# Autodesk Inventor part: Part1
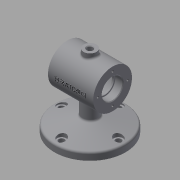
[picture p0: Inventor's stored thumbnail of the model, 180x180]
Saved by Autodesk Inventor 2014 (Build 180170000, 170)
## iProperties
Created: 2018-12
Part Number: Part1
Material: Generic
Document SubType Name: Modeling
Designer: kh
Density: 1 g/cm^3
Appearance: Default
Author: kh
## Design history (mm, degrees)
sketch "Sketch1"
  geometry: C1 r 55 at (0, 0); 1 further point
  constraints: 1 centre point, 1 coincident
  dimensions: "d0" = 110 diameter of C1
extrude "Extrusion1" new body sketch "Sketch1" distance "d1" = 11; taper "d2" = 0 deg
sketch "Sketch2"
  geometry: L1 (-59.309, 75)-(74.881, 75); L2 (-55, 0)-(55, 0) reference; L3 (-35, 75)-(35, 75); L4 (35, 75)-(35, 105); L5 (35, 105)-(-35, 105); L6 (-35, 105)-(-35, 75); L7 (0, 0)-(0, 105)
  constraints: 12 end point, 2 horizontal, 2 parallel, 2 perpendicular, 1 midpoint, 1 point on line, 1 other
  dimensions: "d4" = 75 distance between parallel lines of L2 L1; "d5" = 60 diameter of L5 L1; "d6" = 70 distance between parallel lines of L4 L6
revolve "Revolution1" sketch "Sketch2" stored, may be unused: angle "d7" = 90 deg
sketch "Sketch3"
  geometry: C1 r 12 at (0, 0); 1 further point
  constraints: 1 centre point, 1 coincident
  dimensions: "d8" = 24 diameter of C1
extrude "Extrusion2" join sketch "Sketch3" stored distance "d9" = 10; taper "d10" = 0 deg
sketch "Sketch4"
  geometry: L1 (12, 11)-(12, 45) reference; L2 (55, 11)-(-55, 11) reference; L3 (-12, 11)-(-12, 45) reference; L4 (0, 25.737)-(55, 11); L5 (-35, 105)-(35, 105) reference; L6 (0, 0)-(0, 105); L7 (0, 11)-(55, 11); L8 (0, 25.737)-(0, 11)
  constraints: 8 end point, 2 collinear, 2 midpoint, 2 point on line
  dimensions: "d11" = 165 deg angle of L2 L4
revolve "Revolution2" sketch "Sketch4" stored, may be unused: angle "d12" = 90 deg
sketch "Sketch6"
  geometry: L1 (-63.947, 75)-(66.267, 75); L2 (-35, 105)-(35, 105) reference; L3 (-35, 45)-(35, 45) reference; L4 (-55, 0)-(55, 0) reference; L5 (-35, 45)-(-35, 105) reference; L6 (35, 45)-(35, 105) reference; L7 (-35, 75)-(-23, 75); L8 (-23, 75)-(-23, 90.7); L9 (-23.3, 91)-(-35, 91); L10 (-35, 91)-(-35, 75); L11 (-23, 75)-(-20, 75); L12 (-20, 75)-(-20, 89); L13 (-20, 89)-(-23, 89); L14 (-23, 89)-(-23, 75); L15 (-20, 75)-(20, 75); L16 (20, 75)-(20, 97); L17 (17, 100)-(-17, 100); L18 (-20, 97)-(-20, 75); L19 (20, 75)-(23, 75); L20 (23, 75)-(23, 90.7); L21 (23, 89)-(20, 89); L22 (20, 89)-(20, 75); L23 (23, 75)-(35, 75); L24 (35, 75)-(35, 91); L25 (35, 91)-(23.3, 91); L26 (23, 91)-(23, 75); A1 r 0.3 centre (-23.3, 90.7) between (-23, 90.7) and (-23.3, 91); A2 r 0.3 centre (23.3, 90.7) between (23.3, 91) and (23, 90.7); A3 r 3 centre (-17, 97) between (-17, 100) and (-20, 97); A4 r 3 centre (17, 97) between (20, 97) and (17, 100); 4 further points
  constraints: 42 end point, 10 parallel, 9 point on line, 8 point on circle, 8 tangent, 6 horizontal, 5 perpendicular, 4 centre point, 2 equal radius, 1 midpoint
  dimensions: "d13" = 150 diameter of L4 L1; "d14" = 32 diameter of L9 L1; "d15" = 28 diameter of L13 L1; "d16" = 50 diameter of L17 L1; "d17" = 32 diameter of L25 L1; "d18" = 28 diameter of L21 L1; "d19" = 40 distance of point (20, 100) point (-20, 100); "d20" = 12 distance of point (-23, 91) L9.end; "d21" = 3 distance of L12.end L13.end; "d22" = 3 distance of L21.start L21.end; "d23" = 0.3 radius of A1; "d24" = 3 radius of A3
revolve "Revolution3" sketch "Sketch6" stored, may be unused: angle "d25" = 90 deg
sketch "Sketch8" dims "d27" = 88
  geometry: L1 (0, 0)-(0, 44); C1 r 4.5 at (0, 44); 2 further points
  constraints: 3 coincident, 2 end point, 1 centre point, 1 vertical, 1 vertical alignment, 2 other
  dimensions: "d28" = 9 diameter of C1
extrude "Extrusion3" cut sketch "Sketch8" distance "d29" = 16; taper "d30" = 0 deg
workplane "Work Plane3"
sketch "Sketch11"
  geometry: C1 r 4.5 at (0, 44) reference; C2 r 7 at (0, 44); 1 further point
  constraints: 1 centre point, 1 coincident
  dimensions: "d35" = 14 diameter of C2
extrude "Extrusion4" cut sketch "Sketch11" distance "d36" = 6; taper "d37" = 0 deg
pattern_circular "Circular Pattern1" dims angle "d39" = 360 deg
sketch "Sketch12" dims "d41" = 46
  geometry: L1 (0, 0)-(23, 0); C1 r 16 at (0, 0) reference; C2 r 30 at (0, 0) reference; 2 further points
  constraints: 2 coincident, 2 end point, 1 horizontal, 1 horizontal alignment, 2 other
hole "Hole1" sketch "Sketch12" at (23, 0) diameter "d42" = 3.242; stored, may be unused: countersink angle "d46" = 90 deg, drill point angle "d48" = 118 deg; dims "d43" = 8, "d44" = 4, "d45" = 2, "d47" = 10
pattern_circular "Circular Pattern2" dims angle "d50" = 360 deg
mirror "Mirror1"
workplane "Work Plane4"
sketch "Sketch13"
  geometry: L1 (0, 0)-(0, 55); C1 r 10 at (0, 0); C2 r 5 at (0, 0); 1 further point
  constraints: 2 centre point, 2 coincident, 2 end point, 1 vertical, 1 vertical alignment, 1 other
  dimensions: "d53" = 20 diameter of C1; "d54" = 10 diameter of C2
extrude "Extrusion5" join sketch "Sketch13" stored distance "d55" = 6; taper "d56" = 0 deg
sketch "Sketch14"
  geometry: C1 r 4.5 at (0, 0); 1 further point
  constraints: 1 centre point, 1 coincident
  dimensions: "d57" = 9 diameter of C1
extrude "Extrusion6" cut sketch "Sketch14" stored distance "d58" = 6; taper "d59" = 0 deg
chamfer "Chamfer1" distance "d60" = 1; stored, may be unused: second distance "d61" = 2, angle "d62" = 45 deg
workplane "Work Plane5"
sketch "Sketch15"
  geometry: L1 (-24.887, 3.602)-(24.887, 3.602); L2 (24.887, 3.602)-(24.887, -3.602); L3 (24.887, -3.602)-(-24.887, -3.602); L4 (-24.887, -3.602)-(-24.887, 3.602); L5 (-24.887, 3.602)-(24.887, -3.602); L6 (-35, 30)-(-35, -30) reference; L7 (35, 30)-(-35, 30) reference; 2 further points
  constraints: 2 end point, 1 midpoint, 2 other
  dimensions: "d63" = 35 distance from line of point (0, 0) L6; "d64" = 30 distance from line of point (0, 0) L7
emboss "Emboss1" sketch "Sketch15" dims "d65" = 0.5, "d66" = 0
fillet "Fillet1" dims "d67" = 3
fillet "Fillet2" dims "d68" = 3
fillet "Fillet3" dims "d69" = 3
body "Solid1"
node "Projected Loop2"
other parameters: "d52" = 112
